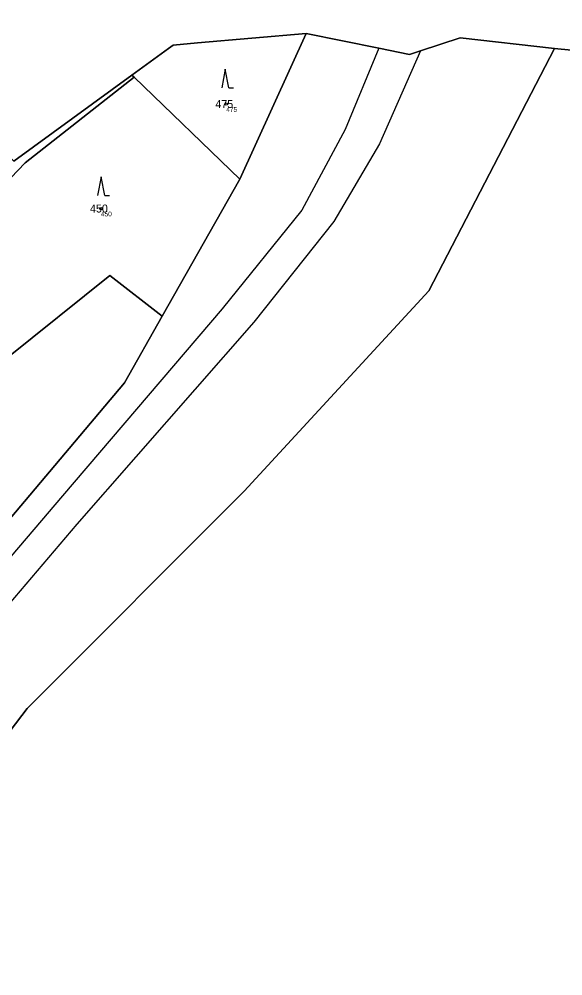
# Model space of a CAD drawing. Extents: x -554500 to -548272, y -1079733 to -1073730.
# Drawn here: x -551489.7 to -551374.3, y -1075724.9 to -1075521.8 of the extents above; entities that cross this region are included whole.
import ezdxf

# ---------------------------------------------------------------- set-up
doc = ezdxf.new("R2010")
doc.units = 0
for name, color, linetype in [('Definiční body', 7, 'Continuous'), ('Hranice parcel', 7, 'Continuous'), ('Parcelní čísla', 7, 'Continuous'), ('Polygon ku', 7, 'Continuous'), ('Polygon parcely', 7, 'Continuous'), ('Vnitřní kresba', 7, 'Continuous'), ('Značky kultur', 7, 'Continuous')]:
    doc.layers.add(name, color=color, linetype=linetype)

msp = doc.modelspace()

# ---------------------------------------------------------------- linework, layer by layer
at = {"layer": 'Definiční body'}
for centre in [(-551445.76, -1075539.84994), (-551472.35, -1075562.02994)]:
    msp.add_circle(centre, 0.25, dxfattribs=at)
at = {"layer": 'Hranice parcel'}
for p, q in [((-551451.89, -1075526.88), (-551428.8, -1075524.85)), ((-551442.88, -1075555.83), (-551428.8, -1075524.85)), ((-551465.77, -1075533.69), (-551458.03, -1075528.04)), ((-551376.14, -1075528.04), (-551372.54, -1075528.44)), ((-551490.82, -1075551.95), (-551465.77, -1075533.69)), ((-551465.77, -1075533.69), (-551465.28, -1075534.16)), ((-551442.88, -1075555.83), (-551465.28, -1075534.16)), ((-551459.35, -1075584.9), (-551442.88, -1075555.83))]:
    msp.add_line(p, q, dxfattribs=at)
for points in [[(-551428.8, -1075524.85), (-551413.37, -1075528.01), (-551406.9, -1075529.33), (-551404.54, -1075528.55), (-551396.16, -1075525.8), (-551376.14, -1075528.04)], [(-551458.03, -1075528.04), (-551457.05, -1075527.33), (-551451.89, -1075526.88)], [(-551376.14, -1075528.04), (-551402.75, -1075579.49), (-551441.98, -1075622.04), (-551488.01, -1075668.18), (-551509.93, -1075696.87), (-551533.46, -1075736.03), (-551537.91, -1075792.05), (-551533.26, -1075824.67), (-551530.47, -1075859.76), (-551529.75, -1075897.45)], [(-551465.28, -1075534.16), (-551488.46, -1075552.33), (-551496.05, -1075560.25), (-551518.81, -1075597.54), (-551525.61, -1075596.45)], [(-551459.35, -1075584.9), (-551470.49, -1075576.27), (-551492.3, -1075593.8), (-551517.28, -1075602.15), (-551525.59, -1075597.39)], [(-551560.75, -1075872.41), (-551564.05, -1075824.19), (-551568.79, -1075795.75), (-551568.78, -1075755.17), (-551558.84, -1075728.67), (-551539.1, -1075684.12), (-551467.34, -1075599.01), (-551459.35, -1075584.9)]]:
    msp.add_lwpolyline(points, dxfattribs=at)
at = {"layer": 'Polygon ku'}
msp.add_lwpolyline([(-551372.54, -1075528.44), (-551376.14, -1075528.04), (-551396.16, -1075525.8), (-551404.54, -1075528.55), (-551406.9, -1075529.33), (-551413.37, -1075528.01), (-551428.8, -1075524.85), (-551451.89, -1075526.88), (-551457.05, -1075527.33), (-551458.03, -1075528.04), (-551465.77, -1075533.69), (-551490.82, -1075551.95), (-551500.16, -1075542.97), (-551504.87, -1075539.17), (-551509.43, -1075536.01), (-551514.4, -1075532.57), (-551549.56, -1075508.24)], dxfattribs=at)
at = {"layer": 'Polygon parcely'}
for points in [[(-551529.75, -1075897.45), (-551530.47, -1075859.76), (-551533.26, -1075824.67), (-551537.91, -1075792.05), (-551533.46, -1075736.03), (-551509.93, -1075696.87), (-551488.01, -1075668.18), (-551441.98, -1075622.04), (-551402.75, -1075579.49), (-551376.14, -1075528.04), (-551396.16, -1075525.8), (-551404.54, -1075528.55), (-551406.9, -1075529.33), (-551413.37, -1075528.01), (-551428.8, -1075524.85), (-551442.88, -1075555.83), (-551459.35, -1075584.9), (-551467.34, -1075599.01), (-551539.1, -1075684.12), (-551558.84, -1075728.67), (-551568.78, -1075755.17), (-551568.79, -1075795.75), (-551564.05, -1075824.19), (-551560.75, -1075872.41)], [(-551372.54, -1075528.44), (-551376.14, -1075528.04), (-551402.75, -1075579.49), (-551441.98, -1075622.04), (-551488.01, -1075668.18), (-551509.93, -1075696.87), (-551533.46, -1075736.03), (-551537.91, -1075792.05), (-551533.26, -1075824.67), (-551530.47, -1075859.76), (-551529.75, -1075897.45)], [(-551496.05, -1075560.25), (-551488.46, -1075552.33), (-551465.28, -1075534.16), (-551465.77, -1075533.69), (-551490.82, -1075551.95)], [(-551558.84, -1075728.67), (-551539.1, -1075684.12), (-551467.34, -1075599.01), (-551459.35, -1075584.9), (-551470.49, -1075576.27), (-551492.3, -1075593.8), (-551517.28, -1075602.15), (-551525.59, -1075597.39), (-551533.17, -1075599.56), (-551538.37, -1075605.21), (-551538.32, -1075616.93), (-551551.82, -1075645.98), (-551566.19, -1075651.07), (-551581.91, -1075665.22), (-551587.04, -1075663.89), (-551594.66, -1075668.19), (-551622.67, -1075692.4), (-551628.96, -1075695.24), (-551639.8, -1075718.91), (-551640.12, -1075723.66), (-551626.96, -1075713.37), (-551568, -1075682.57), (-551547.47, -1075673.1), (-551580.44, -1075787.2)]]:
    msp.add_lwpolyline(points, dxfattribs=at)
for points in [[(-551442.88, -1075555.83), (-551428.8, -1075524.85), (-551451.89, -1075526.88), (-551457.05, -1075527.33), (-551458.03, -1075528.04), (-551465.77, -1075533.69), (-551465.28, -1075534.16)], [(-551525.61, -1075596.45), (-551525.59, -1075597.39), (-551517.28, -1075602.15), (-551492.3, -1075593.8), (-551470.49, -1075576.27), (-551459.35, -1075584.9), (-551442.88, -1075555.83), (-551465.28, -1075534.16), (-551488.46, -1075552.33), (-551496.05, -1075560.25), (-551518.81, -1075597.54)]]:
    msp.add_lwpolyline(points, close=True, dxfattribs=at)
at = {"layer": 'Vnitřní kresba'}
for p, q in [((-551413.37, -1075528.01), (-551420.56, -1075545.24)), ((-551404.54, -1075528.55), (-551413.24, -1075548.29)), ((-551420.56, -1075545.24), (-551429.76, -1075562.39)), ((-551413.24, -1075548.29), (-551422.97, -1075564.78)), ((-551429.76, -1075562.39), (-551446.62, -1075583.35)), ((-551422.97, -1075564.78), (-551439.93, -1075586.17)), ((-551446.62, -1075583.35), (-551480.51, -1075623.04)), ((-551439.93, -1075586.17), (-551477.49, -1075629.07)), ((-551480.51, -1075623.04), (-551515.55, -1075664.04)), ((-551477.49, -1075629.07), (-551510.92, -1075668.3))]:
    msp.add_line(p, q, dxfattribs=at)
at = {"layer": 'Značky kultur'}
for p, q in [((-551445.96, -1075532.43), (-551446.71, -1075536.43)), ((-551445.21, -1075536.43), (-551445.96, -1075532.43)), ((-551445.21, -1075536.43), (-551444.214, -1075536.43)), ((-551472.31, -1075555.27), (-551473.06, -1075559.27)), ((-551471.56, -1075559.27), (-551472.31, -1075555.27)), ((-551471.56, -1075559.27), (-551470.564, -1075559.27))]:
    msp.add_line(p, q, dxfattribs=at)

# ---------------------------------------------------------------- texts
at = {"layer": 'Definiční body'}
for s, p in [('475', (-551445.76, -1075541.506)), ('450', (-551472.35, -1075563.686))]:
    msp.add_text(s, height=0.999996, dxfattribs=at).set_placement(p)
at = {"layer": 'Parcelní čísla'}
for s, p in [('475', (-551448.085, -1075540.7)), ('450', (-551474.675, -1075562.88))]:
    msp.add_text(s, height=1.699998, dxfattribs=at).set_placement(p)

doc.saveas('drawing.dxf')
